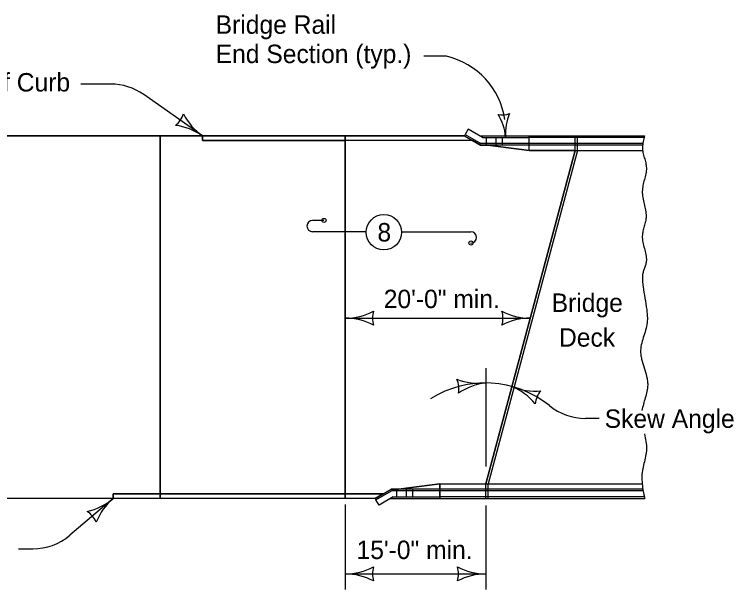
# Model space of a CAD drawing. Extents: x 9234 to 81668, y 5635 to 15999.
# Drawn here: x 17970 to 18595, y 8782 to 9281 of the extents above; entities that cross this region are included whole.
import ezdxf

# ---------------------------------------------------------------- set-up
doc = ezdxf.new("R2010")
doc.units = 0
for name, color, linetype in [('Annotation', 7, 'Continuous'), ('PS_BOLT', 7, 'Continuous'), ('PS_CONST', 7, 'Continuous'), ('PS_DIM', 7, 'Continuous'), ('Revetment', 7, 'Continuous')]:
    doc.layers.add(name, color=color, linetype=linetype)

msp = doc.modelspace()

# ---------------------------------------------------------------- linework, layer by layer
at = {"layer": 'Annotation'}
for p, q in [((18364.15, 9181.52), (18361.47, 9176.88)), ((18376.52, 9174.38), (18364.15, 9181.52)), ((18360.8, 9175.72), (18361.47, 9176.88)), ((18360.8, 9175.72), (18374.72, 9167.68)), ((18361.47, 9176.88), (18375.08, 9169.02)), ((18374.2, 9175.72), (18417.11, 9175.72)), ((18379.58, 9174.38), (18379.58, 9167.68)), ((18388.12, 9174.38), (18388.12, 9167.68)), ((18393.49, 9174.38), (18393.49, 9167.68)), ((18417.11, 9175.72), (18517.15, 9175.72)), ((18417.11, 9162.99), (18417.11, 9175.72)), ((18516.77, 9174.38), (18417.11, 9174.38)), ((18456.9, 9162.99), (18456.9, 9175.72)), ((18456.92, 9162.99), (18456.92, 9175.72)), ((18458.9, 9162.99), (18458.9, 9175.72)), ((18417.11, 9167.68), (18374.72, 9167.68)), ((18417.11, 9169.02), (18375.08, 9169.02)), ((18417.11, 9162.99), (18381.09, 9167.68)), ((18515.82, 9169.02), (18417.11, 9169.02)), ((18515.69, 9167.68), (18417.11, 9167.68)), ((18456.9, 9162.99), (18379.32, 8873.46)), ((18456.92, 9162.99), (18379.34, 8873.46)), ((18417.11, 9162.99), (18515.65, 9162.99)), ((18339.53, 8873.46), (18303.51, 8868.77)), ((18339.53, 8873.46), (18339.53, 8860.72)), ((18339.53, 8862.06), (18339.53, 8873.46)), ((18339.53, 8873.46), (18515.28, 8873.46)), ((18379.32, 8860.72), (18379.32, 8873.46)), ((18379.34, 8860.72), (18379.34, 8873.46)), ((18381.32, 8860.72), (18381.32, 8873.46)), ((18283.22, 8860.73), (18297.14, 8868.77)), ((18283.89, 8859.56), (18297.51, 8867.42)), ((18339.53, 8868.77), (18297.14, 8868.77)), ((18339.53, 8867.42), (18297.51, 8867.42)), ((18302, 8862.06), (18302, 8868.77)), ((18310.54, 8862.06), (18310.54, 8868.77)), ((18315.91, 8862.06), (18315.91, 8868.77)), ((18515.8, 8868.77), (18339.53, 8868.77)), ((18516.01, 8867.42), (18339.53, 8867.42)), ((18298.94, 8862.06), (18286.57, 8854.92)), ((18517.14, 8862.06), (18339.53, 8862.06)), ((18283.22, 8860.73), (18283.89, 8859.56)), ((18286.57, 8854.92), (18283.89, 8859.56)), ((18296.62, 8860.72), (18339.53, 8860.72)), ((18339.53, 8860.72), (18517.57, 8860.72))]:
    msp.add_line(p, q, dxfattribs=at)
for points in [[(18376.52, 9174.38), (18417.11, 9174.38), (18417.11, 9174.38), (18417.11, 9174.38)], [(18298.94, 8862.06), (18339.53, 8862.06), (18339.53, 8862.06), (18339.53, 8862.06)]]:
    msp.add_lwpolyline(points, dxfattribs=at)
at = {"layer": 'PS_CONST'}
for centre in [(18238.75, 9102.31), (18366.42, 9082.64)]:
    msp.add_circle(centre, 1.78, dxfattribs=at)
for centre, radius, start, end in [((18393.78, 9210.38), 16.42, 256.63311, 292.09982), ((18354.11, 9171.61), 42.5, 4.36647, 32.43895), ((18438.87, 9178.08), 42.5, 156.29398, 184.36647)]:
    msp.add_arc(centre, radius, start, end, dxfattribs=at)
at = {"layer": 'PS_DIM'}
for p, q in [((18345.16, 9244.95), (18325.65, 9244.95)), ((18053.39, 9220.7), (18027.65, 9220.7)), ((18133.28, 9175.72), (18082.12, 9211.62)), ((18517.15, 9175.72), (18517.15, 9175.72)), ((18238.75, 9102.31), (18228.92, 9102.31)), ((18275.41, 9092.48), (18228.92, 9092.48)), ((18306.13, 9092.48), (18366.43, 9092.48)), ((18257.28, 9017.39), (18417.9, 9017.39)), ((18379.32, 8974.01), (18379.32, 8888.63)), ((18477.83, 8930.25), (18466.03, 8930.25)), ((18517.21, 8861.81), (18517.57, 8860.72)), ((18055.7, 8860.73), (18017.99, 8828.8)), ((18257.28, 8855.49), (18257.28, 8781.55)), ((18379.32, 8854.76), (18379.32, 8781.55)), ((17973.41, 8816.96), (17985.68, 8816.96)), ((18257.28, 8795.19), (18379.32, 8795.19))]:
    msp.add_line(p, q, dxfattribs=at)
for points in [[(17935.58, 8860.73), (17935.58, 9175.72), (17946.65, 9175.72), (17946.65, 9175.72), (18096.43, 9175.72), (18096.43, 8864.74), (18055.7, 8864.74), (18055.7, 8860.73)], [(18257.28, 8864.74), (18096.43, 8864.74), (18096.43, 9175.72), (18133.28, 9175.72), (18133.28, 9171.7), (18257.28, 9171.7)], [(18257.28, 9175.72), (18257.28, 9171.7), (18133.28, 9171.7), (18133.28, 9175.72)], [(18360.8, 9175.72), (18367.76, 9171.7), (18257.28, 9171.7), (18257.28, 9175.72)], [(18374.72, 9167.68), (18367.76, 9171.7), (18257.28, 9171.7), (18257.28, 8864.74), (18290.16, 8864.74), (18297.14, 8868.77), (18303.51, 8868.77), (18339.53, 8873.46), (18379.32, 8873.46), (18456.9, 9162.99), (18417.11, 9162.99), (18381.09, 9167.68)], [(18055.7, 8860.73), (18055.7, 8864.74), (18096.43, 8864.74), (18096.43, 8860.73)], [(18096.43, 8860.73), (18096.43, 8864.74), (18257.28, 8864.74), (18257.28, 8860.73)], [(18290.16, 8864.74), (18283.22, 8860.73), (18257.28, 8860.73), (18257.28, 8864.74)]]:
    msp.add_lwpolyline(points, close=True, dxfattribs=at)
msp.add_circle((18290.8, 9092), 15.36, dxfattribs=at)
msp.add_circle((18290.8, 9092), 15.36, dxfattribs=at)
for centre, radius, start, end in [((18330.03, 9180.02), 66.66, 8.48278, 76.88228), ((18053.39, 9170.7), 50, 54.93824, 90), ((18097.43, 9200.87), 20.17, 307.20489, 342.67159), ((18163.28, 9218.47), 52.23, 206.86575, 234.93824), ((18103.28, 9132.97), 52.23, 54.93824, 83.01073), ((18228.92, 9097.39), 4.92, 90, 270), ((18366.42, 9087.56), 4.92, 270, 90), ((18257.28, 9069.62), 52.23, 270, 298.07249), ((18301.07, 9017.39), 20.17, 162.26665, 197.73335), ((18374.11, 9017.39), 20.17, 342.26665, 17.73335), ((18417.9, 9069.62), 52.23, 241.92751, 270), ((18257.28, 8965.16), 52.23, 61.92751, 90), ((18417.9, 8965.16), 52.23, 90, 118.07249), ((18378.81, 8872.39), 88.71, 51.03773, 122.32505), ((18335.83, 8955.91), 20.17, 349.07651, 24.54321), ((18373.12, 9012.96), 52.23, 248.73737, 276.80986), ((18385.51, 8909.24), 52.23, 96.80986, 124.88235), ((18421.99, 9006.27), 52.23, 247.49534, 275.56783), ((18382, 8909.77), 52.23, 39.42285, 67.49534), ((18442.45, 8941.26), 20.17, 139.76199, 175.22869), ((18466.03, 8980.25), 50, 231.03773, 270), ((18021.96, 8900.59), 52.23, 282.17459, 310.24708), ((18089.44, 8820.86), 52.23, 130.24708, 158.31957), ((18022.28, 8832.43), 20.17, 22.51373, 57.98043), ((17985.68, 8866.96), 50, 270, 310.24708), ((18257.28, 8847.41), 52.23, 270, 298.07249), ((18301.07, 8795.19), 20.17, 162.26665, 197.73335), ((18335.53, 8795.19), 20.17, 342.26665, 17.73335), ((18379.32, 8847.41), 52.23, 241.92751, 270), ((18257.28, 8742.96), 52.23, 61.92751, 90), ((18379.32, 8742.96), 52.23, 90, 118.07249)]:
    msp.add_arc(centre, radius, start, end, dxfattribs=at)
for points in [[(18517.15, 9175.72), (18516.03, 9170.71), (18515.73, 9168.19), (18515.55, 9165.67), (18515.93, 9161.23), (18517.09, 9156.79), (18518.3, 9152.35), (18518.87, 9147.9), (18518.32, 9142.81), (18517.11, 9137.72), (18515.89, 9132.62), (18515.32, 9127.52), (18515.82, 9122.08), (18516.99, 9116.62), (18518.14, 9111.17), (18518.63, 9105.73), (18518.11, 9101.45), (18517.02, 9097.19), (18515.9, 9092.93), (18515.32, 9088.67), (18515.82, 9083.34), (18517.13, 9078.01), (18518.42, 9072.67), (18518.87, 9067.34), (18518.3, 9064.12), (18517.23, 9060.94), (18516.14, 9057.76), (18515.55, 9054.55), (18515.56, 9049.64), (18515.99, 9044.7), (18517.57, 9034.74), (18519.17, 9024.8), (18519.71, 9017.41), (18519.66, 9014.97), (18518.63, 9008.55), (18516.73, 9002.14), (18514.84, 8995.73), (18513.88, 8989.3), (18514.06, 8985.55), (18514.73, 8981.79), (18516.9, 8974.29), (18519.1, 8966.79), (18519.8, 8963.04), (18519.98, 8961.16), (18520.02, 8959.28), (18519.36, 8953.73), (18517.93, 8948.17), (18516.29, 8942.62), (18515.01, 8937.06)], [(18517.13, 8916.78), (18518.44, 8910.19), (18518.94, 8903.6), (18518.2, 8897.36), (18516.76, 8891.12), (18515.41, 8884.89), (18514.96, 8878.65), (18515.2, 8874.43), (18515.61, 8870.2), (18517.21, 8861.81)]]:
    msp.add_spline(points, degree=3, dxfattribs=at)
at = {"layer": 'Revetment'}
for p, q in [((18360.8, 9175.72), (17935.58, 9175.72)), ((18096.43, 8860.72), (18096.43, 9175.72)), ((18133.28, 9175.72), (18133.28, 9171.7)), ((18257.28, 8860.73), (18257.28, 9175.72)), ((18360.8, 9175.72), (18374.72, 9167.68)), ((18367.78, 9171.7), (18133.28, 9171.7)), ((18374.72, 9167.68), (18381.09, 9167.68)), ((18381.09, 9167.68), (18417.11, 9162.99)), ((18458.9, 9162.99), (18381.32, 8873.46)), ((18417.11, 9162.99), (18456.92, 9162.99)), ((18456.92, 9162.99), (18418.13, 9018.22)), ((18379.32, 8873.46), (18418.13, 9018.22)), ((18303.51, 8868.77), (18339.53, 8873.46)), ((18339.53, 8873.46), (18379.32, 8873.46)), ((18283.22, 8860.73), (18297.14, 8868.77)), ((18297.14, 8868.77), (18303.51, 8868.77)), ((18290.17, 8864.74), (18055.7, 8864.74)), ((18055.7, 8860.73), (18055.7, 8864.74)), ((18283.22, 8860.73), (17613.88, 8860.73))]:
    msp.add_line(p, q, dxfattribs=at)

# ---------------------------------------------------------------- texts
at = {"layer": 'PS_BOLT'}
for s, p in [('End of Curb', (17904.03, 9214.28)), ('8', (18285.21, 9084)), ('20\'-0" min.', (18290.69, 9026.06)), ('Bridge', (18436.59, 9022.8)), ('Deck', (18442.94, 8992.63)), ('Skew Angle', (18482.63, 8922.07)), ('15\'-0" min.', (18267.04, 8808.11))]:
    msp.add_text(s, height=16, dxfattribs=at).set_placement(p)
at = {"layer": 'PS_DIM'}
for s, p in [('Bridge Rail', (18144.66, 9264.41)), ('End Section (typ.)', (18144.66, 9238.96))]:
    msp.add_text(s, height=16, dxfattribs=at).set_placement(p)

doc.saveas('drawing.dxf')
